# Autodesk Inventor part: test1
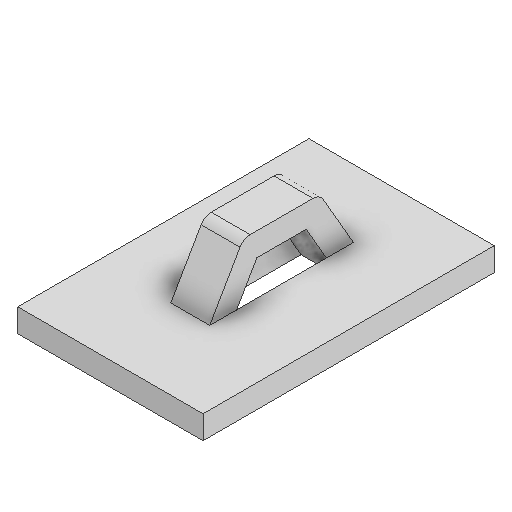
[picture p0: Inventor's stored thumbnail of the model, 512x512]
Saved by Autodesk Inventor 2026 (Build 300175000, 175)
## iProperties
Created: 2025-08
Part Number: test1
Material: Generic
Document SubType Name: Sheet Metal
Designer: sup1
Density: 1 g/cm^3
Sheet Metal Rule: Default
Appearance: Default
Author: sup1
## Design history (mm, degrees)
node "Face1"
  sketch "Sketch1"
    geometry: L1 (12.094, 18.532)-(-12.094, 18.532); L2 (-12.094, 18.532)-(-12.094, -19.478); L3 (-12.094, -19.478)-(12.094, -19.478); L4 (12.094, -19.478)-(12.094, 18.532)
    constraints: 8 end point, 2 parallel, 1 horizontal, 1 perpendicular
sketch "Sketch2"
  geometry: L1 (2.54, 8.89)-(-2.54, 8.89); L2 (-2.54, 8.89)-(-2.54, -6.35); L3 (-2.54, -6.35)-(2.54, -6.35); L4 (2.54, -6.35)-(2.54, 8.89); L5 (2.54, 8.89)-(-2.54, -6.35); L6 (-2.54, 8.89)-(2.54, -6.35); 1 further point
  constraints: 12 end point, 2 parallel, 1 horizontal, 1 midpoint, 1 perpendicular
  dimensions: "Length" = 15.24 distance of L1.end L2.end; "Width" = 5.08 distance of L2.end L3.end
extrude "Extrusion1" cut sketch "Sketch2" distance "d3" = 3.048 (= Thickness); taper "d4" = 0 deg
workplane "Work Plane2"
sketch "Sketch3"
  geometry: L1 (2.64, 7.62)-(12.6, 7.62); L2 (12.6, 7.62)-(17.88, -1.524); L3 (17.88, -1.524)-(15.24, -3.048); L4 (15.24, -3.048)-(10.841, 4.572); L5 (10.841, 4.572)-(4.399, 4.572); L6 (4.399, 4.572)-(0, -3.048); L7 (0, -3.048)-(-2.64, -1.524); L8 (-2.64, -1.524)-(2.64, 7.62); L9 (15.24, 0)-(0, 0) reference; L10 (0, 0)-(15.24, 0) reference; 1 further point
  constraints: 16 end point, 3 parallel, 2 perpendicular, 1 horizontal, 1 midpoint
  dimensions: "Angle" = 60 deg angle of L6 L9; "d14" = 3.048 vertical distance of L6.end point (7.62, 0) (= Thickness); "d15" = 3.048 vertical distance of L3.end point (7.62, 0) (= Thickness); "d16" = 7.62 distance from line of L1 point (7.62, 0) (= Height); "d17" = 4.572 distance from line of L5 point (7.62, 0) (= Height - Thickness); "d18" = 7.62 horizontal distance of L3.end point (7.62, 0) (= 0.5 x Length); "d19" = 60 deg angle of L4 L9 (= Angle); "d20" = 7.62 horizontal distance of L6.end point (7.62, 0) (= 0.5 x Length); "d21" = 3.048 distance between parallel lines of L8 L6 (= Thickness); "d22" = 3.048 distance between parallel lines of L4 L2 (= Thickness)
extrude "Extrusion2" join sketch "Sketch3" stored distance "d12" = 5.08 (= Width); taper "d13" = 0 deg
fillet "Fillet1" dims "d23" = 1.524 (= 0.5 x Thickness)
body "Solid1"
face "Plate1" dims "d0" = 3.048 (= Thickness)
other parameters: "Thickness" = 3.048, "BendRadius" = 3.048 (= Thickness), "BendReliefWidth" = 3.048 (= Thickness), "BendReliefDepth" = 1.524 (= 0.5 x Thickness), "CornerReliefSize" = 12.192 (= 4 x Thickness), "SeamGap" = 0.00508, "MinimumRemnant" = 6.096 (= 2 x Thickness), "TransitionRadius" = 3.048 (= BendRadius), "JacobiRadiusSize" = 3.048 (= BendRadius), "GapSize" = 3.048 (= Thickness), "Height" = 7.62 [user parameter; used in 2 equation terms]
